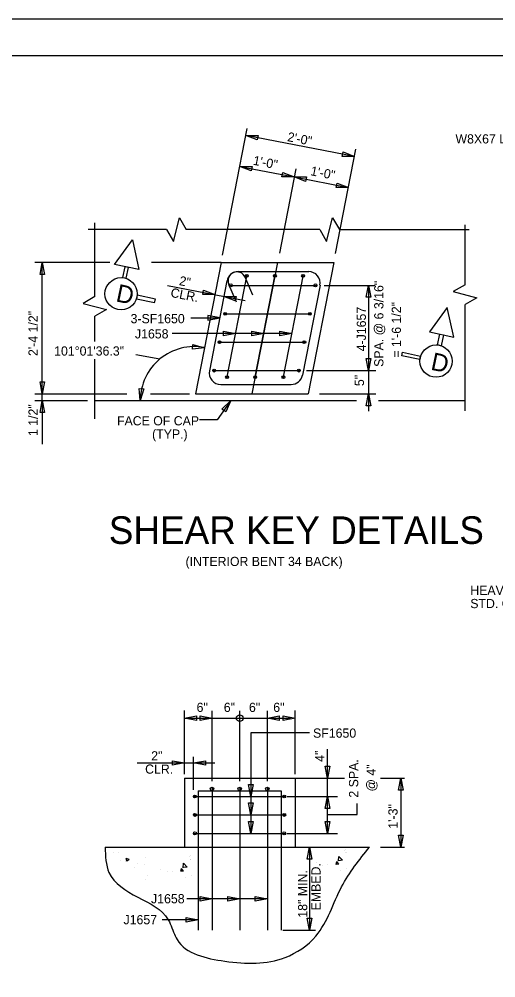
# Model space of a CAD drawing. Extents: x -144.4 to -96.3, y -117.1 to -87.8.
# Drawn here: x -118.31 to -109.69, y -105.14 to -87.8 of the extents above; entities that cross this region are included whole.
import ezdxf

# ---------------------------------------------------------------- set-up
doc = ezdxf.new("R2010")
doc.units = 0
for name, color, linetype in [('BR_AUTO DIMENSION', 7, 'Continuous'), ('BR_BORDER LINES', 7, 'Continuous'), ('BR_CENTER LINES', 7, 'Continuous'), ('BR_CONCRETE', 7, 'Continuous'), ('BR_REBAR', 7, 'Continuous'), ('BR_TEXT', 7, 'Continuous'), ('Default', 7, 'Continuous'), ('Level 31', 7, 'Continuous')]:
    doc.layers.add(name, color=color, linetype=linetype)

msp = doc.modelspace()

# ---------------------------------------------------------------- linework, layer by layer
at = {"layer": 'BR_AUTO DIMENSION'}
for p, q in [((-114.635, -92.07), (-114.188, -89.779)), ((-112.25, -90.286), (-114.213, -89.903)), ((-112.592, -92.039), (-112.225, -90.155)), ((-114.322, -90.465), (-113.341, -90.656)), ((-113.313, -90.511), (-113.609, -92.033)), ((-113.341, -90.656), (-112.36, -90.847)), ((-112.524, -91.606), (-110.174, -91.606)), ((-111.322, -91.606), (-110.882, -91.606)), ((-115.633, -92.615), (-114.225, -92.89)), ((-111.995, -92.615), (-111.995, -94.889)), ((-115.211, -93.203), (-114.686, -93.203)), ((-113.383, -93.485), (-115.547, -93.485)), ((-113.115, -94.156), (-111.862, -94.156)), ((-118.03, -94.574), (-116.365, -94.574)), ((-118.03, -94.574), (-117.755, -94.574)), ((-115.937, -94.574), (-115.235, -94.574)), ((-118.03, -94.699), (-117.078, -94.699)), ((-117.895, -94.699), (-117.895, -95.487)), ((-117.895, -94.699), (-117.895, -95.487)), ((-114.487, -94.699), (-114.735, -95.049)), ((-114.735, -95.049), (-115.054, -95.049)), ((-115.325, -101.453), (-115.325, -100.304)), ((-114.826, -101.578), (-114.826, -100.309)), ((-114.326, -101.578), (-114.326, -100.309)), ((-113.826, -101.578), (-113.826, -100.309)), ((-113.325, -101.453), (-113.325, -100.304)), ((-115.325, -100.439), (-113.41, -100.439)), ((-113.062, -100.708), (-114.126, -100.708)), ((-114.126, -100.708), (-114.126, -102.523)), ((-112.737, -102.523), (-112.737, -101)), ((-115.16, -101.737), (-115.16, -101.138)), ((-116.177, -101.251), (-114.777, -101.251)), ((-113.41, -101.523), (-112.429, -101.523)), ((-111.777, -101.523), (-111.346, -101.523)), ((-111.411, -101.523), (-111.411, -102.773)), ((-113.465, -101.857), (-112.557, -101.857)), ((-112.201, -102.184), (-112.201, -101.986)), ((-112.737, -102.184), (-112.201, -102.184)), ((-113.465, -102.523), (-112.557, -102.523)), ((-113.064, -102.773), (-113.064, -104.273)), ((-111.777, -102.773), (-111.346, -102.773)), ((-113.826, -103.708), (-115.279, -103.708)), ((-115.078, -104.087), (-115.728, -104.087)), ((-113.543, -104.273), (-112.956, -104.273))]:
    msp.add_line(p, q, dxfattribs=at)
for points in [[(-114.008, -89.985), (-114.213, -89.903), (-113.992, -89.904)], [(-112.455, -90.203), (-112.25, -90.286), (-112.471, -90.285)], [(-114.117, -90.547), (-114.322, -90.465), (-114.102, -90.465)], [(-113.546, -90.574), (-113.341, -90.656), (-113.561, -90.655)], [(-113.136, -90.738), (-113.341, -90.656), (-113.12, -90.656)], [(-112.564, -90.765), (-112.36, -90.847), (-112.58, -90.847)], [(-117.936, -92.416), (-117.895, -92.199), (-117.853, -92.416)], [(-114.979, -92.7), (-114.774, -92.783), (-114.995, -92.782)], [(-112.037, -92.831), (-111.995, -92.615), (-111.953, -92.831)], [(-114.406, -92.897), (-114.61, -92.815), (-114.39, -92.815)], [(-114.903, -93.244), (-114.686, -93.203), (-114.903, -93.161)], [(-114.618, -93.444), (-114.401, -93.485), (-114.618, -93.527)], [(-114.109, -93.444), (-113.892, -93.485), (-114.109, -93.527)], [(-113.599, -93.444), (-113.383, -93.485), (-113.599, -93.527)], [(-115.174, -93.685), (-114.961, -93.742), (-115.18, -93.768)], [(-111.953, -93.94), (-111.995, -94.156), (-112.037, -93.94)], [(-117.853, -94.358), (-117.895, -94.574), (-117.936, -94.358)], [(-117.853, -94.358), (-117.895, -94.574), (-117.936, -94.358)], [(-116.058, -94.489), (-116.123, -94.699), (-116.141, -94.479)], [(-112.037, -94.791), (-111.995, -94.574), (-111.953, -94.791)], [(-117.936, -94.916), (-117.895, -94.699), (-117.853, -94.916)], [(-117.936, -94.916), (-117.895, -94.699), (-117.853, -94.916)], [(-114.646, -94.851), (-114.487, -94.699), (-114.578, -94.9)], [(-115.109, -100.481), (-115.325, -100.439), (-115.109, -100.397)], [(-115.043, -100.397), (-114.826, -100.439), (-115.043, -100.481)], [(-113.61, -100.481), (-113.826, -100.439), (-113.61, -100.397)], [(-113.542, -100.397), (-113.325, -100.439), (-113.542, -100.481)], [(-115.542, -101.209), (-115.325, -101.251), (-115.542, -101.292)], [(-114.943, -101.292), (-115.16, -101.251), (-114.943, -101.209)], [(-112.695, -101.307), (-112.737, -101.523), (-112.778, -101.307)], [(-111.453, -101.74), (-111.411, -101.523), (-111.37, -101.74)], [(-114.085, -101.64), (-114.126, -101.857), (-114.168, -101.64)], [(-112.778, -102.073), (-112.737, -101.857), (-112.695, -102.073)], [(-114.085, -101.973), (-114.126, -102.19), (-114.168, -101.973)], [(-114.085, -102.307), (-114.126, -102.523), (-114.168, -102.307)], [(-112.695, -102.307), (-112.737, -102.523), (-112.778, -102.307)], [(-111.37, -102.557), (-111.411, -102.773), (-111.453, -102.557)], [(-113.106, -102.99), (-113.064, -102.773), (-113.023, -102.99)], [(-115.043, -103.666), (-114.826, -103.708), (-115.043, -103.749)], [(-114.543, -103.666), (-114.326, -103.708), (-114.543, -103.749)], [(-114.043, -103.666), (-113.826, -103.708), (-114.043, -103.749)], [(-115.294, -104.045), (-115.078, -104.087), (-115.294, -104.128)], [(-113.023, -104.057), (-113.064, -104.273), (-113.106, -104.057)]]:
    msp.add_lwpolyline(points, close=True, dxfattribs=at)
for points in [[(-115.649, -91.606), (-115.525, -91.82), (-115.415, -91.395), (-115.294, -91.606)], [(-112.879, -91.606), (-112.755, -91.82), (-112.645, -91.395), (-112.524, -91.606)], [(-110.251, -92.605), (-110.466, -92.728), (-110.04, -92.839), (-110.251, -92.959)], [(-116.943, -92.818), (-117.158, -92.942), (-116.732, -93.053), (-116.943, -93.173)]]:
    msp.add_lwpolyline(points, dxfattribs=at)
msp.add_circle((-114.326, -100.439), 0.06, dxfattribs=at)
at = {"layer": 'BR_BORDER LINES'}
msp.add_line((-97.136, -88.468), (-141.912, -88.468), dxfattribs=at)
at = {"layer": 'BR_CENTER LINES'}
msp.add_line((-113.641, -92.199), (-114.104, -94.574), dxfattribs=at)
at = {"layer": 'BR_CONCRETE'}
for p, q in [((-114.66, -92.199), (-115.123, -94.574)), ((-114.66, -92.199), (-112.623, -92.199)), ((-112.623, -92.199), (-113.085, -94.574)), ((-115.123, -94.574), (-113.085, -94.574)), ((-116.943, -94.699), (-112.215, -94.699)), ((-111.813, -94.699), (-110.251, -94.699)), ((-115.325, -101.523), (-113.325, -101.523)), ((-115.325, -101.523), (-115.325, -102.773)), ((-113.325, -101.523), (-113.325, -102.773)), ((-116.759, -102.773), (-111.979, -102.773)), ((-116.606, -102.87), (-116.606, -102.87)), ((-116.515, -102.868), (-116.515, -102.868)), ((-116.029, -102.951), (-116.029, -102.951)), ((-115.236, -102.95), (-115.236, -102.95)), ((-115.214, -102.931), (-115.214, -102.931)), ((-112.541, -103.019), (-112.532, -102.939)), ((-112.467, -103.007), (-112.532, -102.939)), ((-112.429, -102.825), (-112.429, -102.825)), ((-112.409, -102.877), (-112.409, -102.877)), ((-112.407, -102.806), (-112.407, -102.806)), ((-112.401, -102.873), (-112.401, -102.873)), ((-116.474, -103.021), (-116.474, -103.021)), ((-116.382, -103.034), (-116.382, -103.034)), ((-116.323, -102.998), (-116.381, -102.976)), ((-116.364, -103.026), (-116.381, -102.976)), ((-116.323, -102.998), (-116.364, -103.026)), ((-116.174, -103.061), (-116.174, -103.061)), ((-116.046, -103.08), (-116.046, -103.08)), ((-115.348, -103.144), (-115.339, -103.064)), ((-115.274, -103.132), (-115.339, -103.064)), ((-115.216, -103.002), (-115.216, -103.002)), ((-115.208, -102.998), (-115.208, -102.998)), ((-112.944, -103.057), (-112.944, -103.057)), ((-112.827, -103.096), (-112.827, -103.096)), ((-112.736, -103.084), (-112.736, -103.084)), ((-112.582, -103.084), (-112.572, -103.032)), ((-112.532, -103.08), (-112.582, -103.084)), ((-112.532, -103.08), (-112.572, -103.032)), ((-112.467, -103.007), (-112.541, -103.018)), ((-116.229, -103.134), (-116.229, -103.134)), ((-115.999, -103.277), (-115.999, -103.277)), ((-115.751, -103.182), (-115.751, -103.182)), ((-115.634, -103.221), (-115.634, -103.221)), ((-115.543, -103.209), (-115.543, -103.209)), ((-115.389, -103.209), (-115.379, -103.157)), ((-115.339, -103.205), (-115.389, -103.209)), ((-115.339, -103.205), (-115.379, -103.157)), ((-115.274, -103.132), (-115.348, -103.143)), ((-115.206, -103.279), (-115.206, -103.279)), ((-112.949, -103.222), (-112.949, -103.222)), ((-112.858, -103.219), (-112.858, -103.219)), ((-112.504, -103.203), (-112.504, -103.203)), ((-112.399, -103.154), (-112.399, -103.154)), ((-116.036, -103.357), (-116.036, -103.357)), ((-115.311, -103.328), (-115.311, -103.328))]:
    msp.add_line(p, q, dxfattribs=at)
msp.add_spline([(-116.759, -102.773), (-116.689, -103.232), (-116.168, -103.678), (-115.618, -104.085), (-115.58, -104.161), (-115.457, -104.445), (-114.595, -104.834), (-113.506, -104.768), (-112.947, -104.379), (-112.483, -103.488), (-111.979, -102.773)], degree=3, dxfattribs=at)
at = {"layer": 'BR_REBAR'}
for p, q in [((-114.351, -92.366), (-113.078, -92.366)), ((-114.556, -92.535), (-114.872, -94.16)), ((-114.56, -94.299), (-114.193, -92.418)), ((-114.09, -92.793), (-114.228, -92.47)), ((-114.051, -94.299), (-113.684, -92.418)), ((-113.541, -94.299), (-113.175, -92.418)), ((-114.385, -92.92), (-114.523, -92.597)), ((-114.514, -92.615), (-112.931, -92.615)), ((-112.873, -92.614), (-113.19, -94.239)), ((-114.614, -93.129), (-113.031, -93.129)), ((-114.714, -93.642), (-113.131, -93.642)), ((-114.814, -94.156), (-113.231, -94.156)), ((-114.668, -94.408), (-113.394, -94.408)), ((-114.826, -101.69), (-114.826, -104.273)), ((-114.326, -101.69), (-114.326, -104.273)), ((-113.826, -101.69), (-113.826, -104.273)), ((-115.16, -101.857), (-113.493, -101.857)), ((-115.078, -101.752), (-115.078, -104.273)), ((-115.078, -101.752), (-113.575, -101.752)), ((-113.575, -101.752), (-113.575, -104.273)), ((-115.16, -102.19), (-113.493, -102.19)), ((-115.16, -102.523), (-113.493, -102.523))]:
    msp.add_line(p, q, dxfattribs=at)
for centre, radius in [((-114.198, -92.444), 0.026), ((-113.689, -92.444), 0.026), ((-113.18, -92.444), 0.026), ((-114.488, -92.615), 0.026), ((-112.957, -92.615), 0.026), ((-114.588, -93.129), 0.026), ((-113.057, -93.129), 0.026), ((-114.688, -93.642), 0.026), ((-113.157, -93.642), 0.026), ((-114.788, -94.156), 0.026), ((-114.555, -94.274), 0.026), ((-114.046, -94.274), 0.026), ((-113.536, -94.274), 0.026), ((-113.257, -94.156), 0.026), ((-114.826, -101.721), 0.0313), ((-114.326, -101.721), 0.0313), ((-113.826, -101.721), 0.0313), ((-115.134, -101.857), 0.026), ((-113.519, -101.857), 0.026), ((-115.134, -102.19), 0.026), ((-113.519, -102.19), 0.026), ((-115.134, -102.523), 0.026), ((-113.519, -102.523), 0.026)]:
    msp.add_circle(centre, radius, dxfattribs=at)
for centre, radius, start, end in [((-114.351, -92.574), 0.208, 90, 168.9733), ((-114.376, -92.533), 0.161, 23.2362, 203.2362), ((-113.078, -92.574), 0.208, 348.9733, 90), ((-114.668, -94.199), 0.208, 168.9733, 270), ((-113.394, -94.199), 0.208, 270, 348.9733)]:
    msp.add_arc(centre, radius, start, end, dxfattribs=at)
at = {"layer": 'BR_TEXT'}
for points in [[(-116.589, -92.239), (-116.267, -91.795), (-116.149, -92.331)], [(-116.377, -92.488), (-116.336, -92.292), (-116.402, -92.278), (-116.443, -92.474)], [(-115.864, -92.927), (-115.851, -92.862), (-116.177, -92.794), (-116.191, -92.859)], [(-110.454, -93.55), (-110.572, -93.014), (-110.895, -93.457)], [(-110.748, -93.693), (-110.707, -93.497), (-110.642, -93.51), (-110.682, -93.706)], [(-111.394, -93.89), (-111.38, -93.824), (-111.054, -93.893), (-111.067, -93.958)]]:
    msp.add_lwpolyline(points, close=True, dxfattribs=at)
for centre in [(-116.47, -92.767), (-110.775, -93.985)]:
    msp.add_circle(centre, 0.292, dxfattribs=at)
at = {"layer": 'Default'}
for p, q in [((-116.943, -92.818), (-116.943, -91.487)), ((-115.649, -91.606), (-117.068, -91.606)), ((-112.879, -91.606), (-115.294, -91.606)), ((-110.251, -92.605), (-110.251, -91.52)), ((-116.674, -92.199), (-118.03, -92.199)), ((-117.895, -94.699), (-117.895, -92.199)), ((-114.66, -92.199), (-115.921, -92.199)), ((-112.799, -92.615), (-111.874, -92.615)), ((-110.251, -94.883), (-110.251, -92.959)), ((-116.943, -93.632), (-116.943, -93.173)), ((-116.201, -93.864), (-115.768, -93.946)), ((-116.943, -95.028), (-116.943, -93.947)), ((-112.88, -94.574), (-111.862, -94.574))]:
    msp.add_line(p, q, dxfattribs=at)
msp.add_arc((-115.147, -94.699), 0.976, 78.9733, 180, dxfattribs=at)
at = {"layer": 'Level 31'}
msp.add_lwpolyline([(-144.35, -117.062), (-96.47, -117.062), (-96.47, -87.803), (-144.35, -87.803)], close=True, dxfattribs=at)

# ---------------------------------------------------------------- texts
at = {"layer": 'BR_AUTO DIMENSION'}
for s, height, rotation, p in [('2\'-0"', 0.1667, 348.9733, (-113.474, -90.005)), ('1\'-0"', 0.1667, 348.9733, (-114.094, -90.432)), ('1\'-0"', 0.1667, 348.9733, (-113.055, -90.622)), ('2"', 0.1667, 348.9733, (-115.431, -92.608)), ('SPA. @ 6 3/16"', 0.16667, 90, (-111.727, -94.089)), ('CLR.', 0.1667, 348.9733, (-115.586, -92.822)), ('4-J1657', 0.1667, 90, (-112.043, -93.808)), ('= 1\'-6 1/2"', 0.16667, 90, (-111.41, -93.923)), ('2\'-4 1/2"', 0.1667, 90, (-117.978, -93.893)), ('5"', 0.1667, 90, (-112.078, -94.437)), ('1 1/2"', 0.1667, 90, (-117.978, -95.34)), ('1 1/2"', 0.1667, 90, (-117.978, -95.34)), ('6"', 0.1667, 360, (-115.105, -100.328)), ('6"', 0.1667, 360, (-114.613, -100.328)), ('6"', 0.1667, 360, (-114.158, -100.328)), ('6"', 0.1667, 360, (-113.719, -100.328)), ('2"', 0.1667, 360, (-115.926, -101.205)), ('4"', 0.1667, 90, (-112.795, -101.23)), ('2 SPA.', 0.1667, 90, (-112.183, -101.877)), ('CLR.', 0.1667, 360, (-116.036, -101.445)), ('@ 4"', 0.1667, 90, (-111.866, -101.767)), ('1\'-3"', 0.1667, 90, (-111.471, -102.439)), ('EMBED.', 0.1667, 90, (-112.864, -103.916)), ('18" MIN.', 0.1667, 90, (-113.104, -104.048))]:
    msp.add_text(s, height=height, rotation=rotation, dxfattribs=at).set_placement(p)
for s, height, p in [('W8X67 L = 1\'-2" (TYP.)', 0.16625, (-110.424, -90.05)), ('3-SF1650', 0.1667, (-116.299, -93.3)), ('J1658', 0.1667, (-116.22, -93.575)), ('101%%D01\'36.3"', 0.16666, (-117.681, -93.885)), ('FACE OF CAP', 0.16633, (-116.544, -95.147)), ('(TYP.)', 0.1663, (-115.91, -95.387)), ('(INTERIOR BENT 34 BACK)', 0.16625, (-115.305, -97.69)), ('HEAVY HEX NUT WITH ', 0.16625, (-110.156, -98.211)), ('STD. CUT WASHER (TYP.)', 0.16625, (-110.156, -98.451)), ('SF1650', 0.1667, (-113, -100.794)), ('J1658', 0.1667, (-115.929, -103.788)), ('J1657', 0.1667, (-116.427, -104.167))]:
    msp.add_text(s, height=height, dxfattribs=at).set_placement(p)
at = {"layer": 'BR_TEXT'}
for p in [(-116.579, -92.902), (-110.886, -94.138)]:
    msp.add_text('D', height=0.32, rotation=348.1911, dxfattribs=at).set_placement(p)
msp.add_text('SHEAR KEY DETAILS', height=0.49875, dxfattribs=at).set_placement((-116.693, -97.29))

doc.saveas('drawing.dxf')
